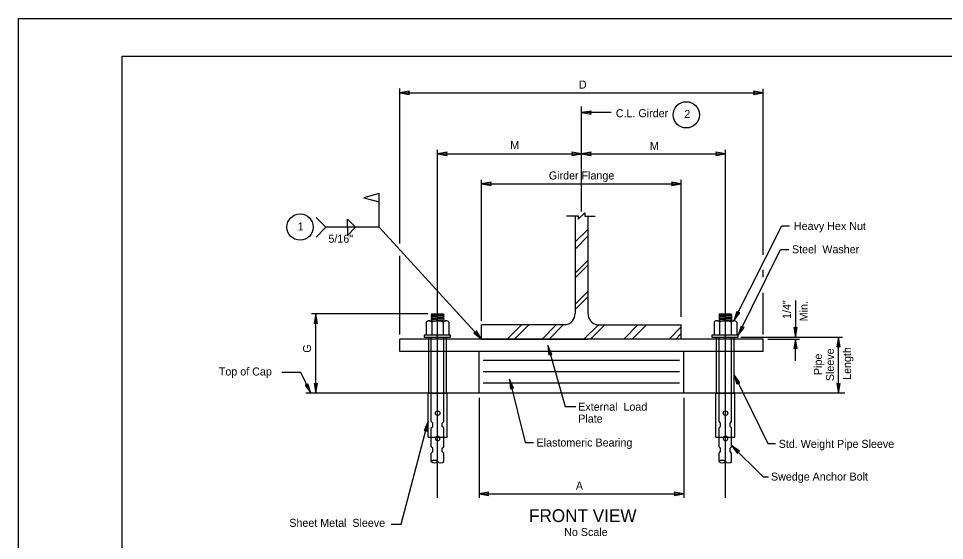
# Model space of a CAD drawing. Extents: x -193 to 149, y 507 to 725.
# Drawn here: x -192.5 to -47.9, y 643.6 to 725.2 of the extents above; entities that cross this region are included whole.
import ezdxf

# ---------------------------------------------------------------- set-up
doc = ezdxf.new("R2010")
doc.units = 0
for name, color, linetype in [('border', 7, 'Continuous'), ('Border 2660-Hwy18 - Level 62', 7, 'Continuous'), ('Level 20', 7, 'Continuous'), ('Level 21', 7, 'Continuous'), ('Level 31', 7, 'Continuous'), ('Level 40', 7, 'Continuous'), ('Level 41', 7, 'Continuous'), ('Level 42', 7, 'Continuous'), ('Level 43', 7, 'Continuous')]:
    doc.layers.add(name, color=color, linetype=linetype)

msp = doc.modelspace()

# ---------------------------------------------------------------- linework, layer by layer
at = {"layer": 'border'}
for p, q in [((-176.33, 719.31), (143.78, 719.31)), ((-176.33, 513.86), (-176.33, 719.31))]:
    msp.add_line(p, q, dxfattribs=at)
at = {"layer": 'Border 2660-Hwy18 - Level 62'}
msp.add_lwpolyline([(-192.53, 725.17), (148.65, 725.17), (148.65, 507.07), (-192.53, 507.07)], close=True, dxfattribs=at)
at = {"layer": 'Level 20'}
for p, q in [((-104.63, 695), (-104.63, 711.42)), ((-127.1, 650.25), (-127.1, 704.67)), ((-82.15, 650.25), (-82.15, 704.67))]:
    msp.add_line(p, q, dxfattribs=at)
at = {"layer": 'Level 21'}
msp.add_line((-63.52, 666.64), (-147.67, 666.64), dxfattribs=at)
at = {"layer": 'Level 31'}
for p, q in [((-105.61, 694.36), (-105.61, 679.08)), ((-103.64, 694.26), (-103.64, 679.08)), ((-128.02, 679), (-128.08, 678.89)), ((-128.08, 678.89), (-126.12, 678.89)), ((-128.08, 678.87), (-128.08, 678.89)), ((-126.16, 678.79), (-128.08, 678.88)), ((-126.16, 678.59), (-128.08, 678.68)), ((-126.16, 678.41), (-128.08, 678.5)), ((-126.16, 678.22), (-128.08, 678.32)), ((-128.02, 679), (-126.2, 679)), ((-126.2, 679), (-126.12, 678.89)), ((-126.12, 678.87), (-126.12, 678.89)), ((-83.07, 679), (-83.14, 678.89)), ((-83.14, 678.89), (-81.17, 678.89)), ((-83.14, 678.87), (-83.14, 678.89)), ((-81.21, 678.79), (-83.14, 678.88)), ((-81.21, 678.59), (-83.14, 678.68)), ((-81.21, 678.41), (-83.14, 678.5)), ((-81.21, 678.22), (-83.14, 678.32)), ((-83.07, 679), (-81.25, 679)), ((-81.25, 679), (-81.17, 678.89)), ((-81.17, 678.87), (-81.17, 678.89)), ((-128.87, 677.71), (-128.87, 675.67)), ((-128.44, 677.95), (-125.75, 677.95)), ((-126.16, 678.04), (-128.08, 678.13)), ((-128.01, 677.71), (-128.01, 675.67)), ((-126.2, 677.71), (-126.2, 675.67)), ((-125.33, 677.71), (-125.33, 675.67)), ((-107.08, 677.32), (-120.21, 677.32)), ((-120.21, 675.09), (-120.21, 677.32)), ((-102.17, 677.32), (-89.04, 677.32)), ((-89.04, 675.09), (-89.04, 677.32)), ((-83.92, 677.71), (-83.92, 675.67)), ((-83.49, 677.95), (-80.8, 677.95)), ((-81.21, 678.04), (-83.14, 678.13)), ((-83.06, 677.71), (-83.06, 675.67)), ((-81.25, 677.71), (-81.25, 675.67)), ((-80.38, 677.71), (-80.38, 675.67)), ((-128.48, 673.12), (-128.48, 675.38)), ((-128.2, 675.38), (-126.03, 675.38)), ((-128.08, 673.12), (-128.08, 675.38)), ((-126.12, 673.12), (-126.12, 675.38)), ((-125.72, 673.12), (-125.72, 675.38)), ((-83.53, 673.12), (-83.53, 675.38)), ((-83.25, 675.38), (-81.08, 675.38)), ((-83.14, 673.12), (-83.14, 675.38)), ((-81.17, 673.12), (-81.17, 675.38)), ((-80.77, 673.12), (-80.77, 675.38)), ((-76.25, 675.09), (-133, 675.09)), ((-133, 673.12), (-133, 675.09)), ((-120.21, 675.09), (-103.64, 675.09)), ((-89.04, 675.09), (-105.61, 675.09)), ((-76.25, 673.12), (-76.25, 675.09)), ((-76.25, 673.12), (-133, 673.12)), ((-128.48, 666.64), (-128.48, 673.12)), ((-128.08, 666.64), (-128.08, 673.12)), ((-126.12, 666.64), (-126.12, 673.12)), ((-125.72, 666.64), (-125.72, 673.12)), ((-120.61, 666.64), (-120.61, 673.12)), ((-88.65, 666.64), (-88.65, 673.12)), ((-83.53, 666.64), (-83.53, 673.12)), ((-83.14, 666.64), (-83.14, 673.12)), ((-81.17, 666.64), (-81.17, 673.12)), ((-80.77, 666.64), (-80.77, 673.12)), ((-119.96, 671.79), (-89.29, 671.79)), ((-119.96, 670.02), (-89.29, 670.02)), ((-119.96, 668.25), (-89.29, 668.25)), ((-128.57, 659.75), (-128.57, 666.64)), ((-128.57, 666.64), (-125.62, 666.64)), ((-128.48, 666.64), (-125.72, 666.64)), ((-128.08, 662.22), (-128.08, 666.64)), ((-126.12, 662.22), (-126.12, 666.64)), ((-125.62, 659.75), (-125.62, 666.64)), ((-83.62, 659.75), (-83.62, 666.64)), ((-83.62, 666.64), (-80.67, 666.64)), ((-83.53, 666.64), (-80.77, 666.64)), ((-83.14, 662.22), (-83.14, 666.64)), ((-81.17, 662.22), (-81.17, 666.64)), ((-80.67, 659.75), (-80.67, 666.64)), ((-127.84, 661.95), (-128.08, 662.22)), ((-128.08, 661.19), (-127.84, 661.44)), ((-128.08, 659.75), (-128.08, 661.19)), ((-127.84, 661.44), (-127.84, 661.95)), ((-126.37, 661.95), (-126.12, 662.22)), ((-126.37, 661.44), (-126.37, 661.95)), ((-126.12, 661.19), (-126.37, 661.44)), ((-126.12, 659.75), (-126.12, 661.19)), ((-82.89, 661.95), (-83.14, 662.22)), ((-83.14, 661.19), (-82.89, 661.44)), ((-83.14, 659.75), (-83.14, 661.19)), ((-82.89, 661.44), (-82.89, 661.95)), ((-81.42, 661.95), (-81.17, 662.22)), ((-81.42, 661.44), (-81.42, 661.95)), ((-81.17, 661.19), (-81.42, 661.44)), ((-81.17, 659.75), (-81.17, 661.19)), ((-128.57, 659.75), (-125.62, 659.75)), ((-128.08, 658.26), (-128.08, 659.75)), ((-126.12, 658.26), (-126.12, 659.75)), ((-83.62, 659.75), (-80.67, 659.75)), ((-83.14, 658.26), (-83.14, 659.75)), ((-81.17, 658.26), (-81.17, 659.75)), ((-127.84, 658.01), (-128.08, 658.26)), ((-127.84, 657.51), (-127.84, 658.01)), ((-126.37, 658.01), (-126.12, 658.26)), ((-126.37, 657.51), (-126.37, 658.01)), ((-82.89, 658.01), (-83.14, 658.26)), ((-82.89, 657.51), (-82.89, 658.01)), ((-81.42, 658.01), (-81.17, 658.26)), ((-81.42, 657.51), (-81.42, 658.01)), ((-128.08, 657.24), (-127.84, 657.51)), ((-128.08, 655.95), (-128.08, 657.24)), ((-126.12, 657.24), (-126.37, 657.51)), ((-126.12, 655.95), (-126.12, 657.24)), ((-83.14, 657.24), (-82.89, 657.51)), ((-83.14, 655.95), (-83.14, 657.24)), ((-81.17, 657.24), (-81.42, 657.51)), ((-81.17, 655.95), (-81.17, 657.24))]:
    msp.add_line(p, q, dxfattribs=at)
for points in [[(-128.08, 678.87), (-128.05, 678.77), (-128.08, 678.68)], [(-128.08, 678.68), (-128.05, 678.59), (-128.08, 678.5)], [(-128.08, 678.5), (-128.05, 678.41), (-128.08, 678.32)], [(-128.08, 678.32), (-128.05, 678.22), (-128.08, 678.13)], [(-126.12, 678.87), (-126.16, 678.77), (-126.12, 678.68)], [(-126.12, 678.68), (-126.16, 678.59), (-126.12, 678.5)], [(-126.12, 678.5), (-126.16, 678.41), (-126.12, 678.32)], [(-126.12, 678.32), (-126.16, 678.22), (-126.12, 678.13)], [(-83.14, 678.87), (-83.1, 678.77), (-83.14, 678.68)], [(-83.14, 678.68), (-83.1, 678.59), (-83.14, 678.5)], [(-83.14, 678.5), (-83.1, 678.41), (-83.14, 678.32)], [(-83.14, 678.32), (-83.1, 678.22), (-83.14, 678.13)], [(-81.17, 678.87), (-81.21, 678.77), (-81.17, 678.68)], [(-81.17, 678.68), (-81.21, 678.59), (-81.17, 678.5)], [(-81.17, 678.5), (-81.21, 678.41), (-81.17, 678.32)], [(-81.17, 678.32), (-81.21, 678.22), (-81.17, 678.13)], [(-128.08, 678.13), (-128.05, 678.04), (-128.08, 677.95)], [(-126.12, 678.13), (-126.16, 678.04), (-126.12, 677.95)], [(-83.14, 678.13), (-83.1, 678.04), (-83.14, 677.95)], [(-81.17, 678.13), (-81.21, 678.04), (-81.17, 677.95)]]:
    msp.add_lwpolyline(points, dxfattribs=at)
for points in [[(-125.08, 675.38), (-125.08, 675.67), (-129.2, 675.67), (-129.2, 675.38)], [(-80.13, 675.38), (-80.13, 675.67), (-84.25, 675.67), (-84.25, 675.38)]]:
    msp.add_lwpolyline(points, close=True, dxfattribs=at)
for centre in [(-127.08, 663.51), (-82.13, 663.51)]:
    msp.add_circle(centre, 0.356, dxfattribs=at)
for centre, radius, start, end in [((-107.38, 679.06), 1.76, 279.5, 0), ((-101.87, 679.06), 1.76, 180, 260.5), ((-128.44, 677.44), 0.511, 32.004, 147.996), ((-127.1, 676.11), 1.84, 60.5577, 119.4423), ((-125.76, 677.44), 0.511, 32.004, 147.996), ((-83.49, 677.44), 0.511, 32.004, 147.996), ((-82.15, 676.11), 1.84, 60.5577, 119.4423), ((-80.81, 677.44), 0.511, 32.004, 147.996), ((-127.08, 659.56), 0.356, 147.5341, 32.4659), ((-127.08, 659.56), 0.356, 32.4659, 147.5341), ((-82.13, 659.56), 0.356, 147.5341, 32.4659), ((-82.13, 659.56), 0.356, 32.4659, 147.5341), ((-127.59, 655.38), 0.751, 49.0496, 130.9504), ((-127.59, 656.51), 0.751, 229.0496, 310.9504), ((-126.61, 656.51), 0.751, 229.0496, 310.9504), ((-82.64, 655.38), 0.751, 49.0496, 130.9504), ((-82.64, 656.51), 0.751, 229.0496, 310.9504), ((-81.66, 656.51), 0.751, 229.0496, 310.9504)]:
    msp.add_arc(centre, radius, start, end, dxfattribs=at)
at = {"layer": 'Level 40'}
msp.add_circle((-88.26, 710.12), 2.05, dxfattribs=at)
at = {"layer": 'Level 42'}
for p, q in [((-105.61, 690.25), (-103.64, 692.22)), ((-105.61, 689.15), (-103.64, 691.15)), ((-105.61, 685.4), (-103.64, 687.37)), ((-105.61, 684.64), (-103.64, 686.61)), ((-105.61, 680.52), (-103.64, 682.49)), ((-105.61, 679.71), (-103.64, 681.7)), ((-116.21, 675.09), (-113.98, 677.32)), ((-115.08, 675.09), (-112.85, 677.32)), ((-110.78, 675.09), (-108.56, 677.32)), ((-109.68, 675.09), (-107.46, 677.32)), ((-104.23, 675.09), (-101.99, 677.32)), ((-103.2, 675.09), (-100.97, 677.32)), ((-98.01, 675.09), (-95.8, 677.32)), ((-96.72, 675.09), (-94.48, 677.32)), ((-90.92, 675.09), (-89.04, 676.99)), ((-89.87, 675.09), (-89.04, 675.93))]:
    msp.add_line(p, q, dxfattribs=at)
at = {"layer": 'Level 43'}
for p, q in [((-133, 700.65), (-133, 714.21)), ((-133, 713.57), (-76.25, 713.57)), ((-76.25, 701.13), (-76.25, 714.19)), ((-99.98, 710.46), (-104.63, 710.46)), ((-127.1, 704.03), (-104.63, 704.03)), ((-104.63, 704.03), (-82.15, 704.03)), ((-133, 690.01), (-133, 700.65)), ((-120.21, 677.95), (-120.21, 699.98)), ((-89.04, 678.53), (-89.04, 699.98)), ((-76.25, 688.26), (-76.25, 701.13)), ((-120.21, 699.33), (-89.04, 699.33)), ((-136.21, 692.54), (-136.21, 697.81)), ((-144.55, 692.54), (-146.07, 694.06)), ((-141.17, 692.54), (-141.17, 693.8)), ((-141.17, 693.8), (-139.91, 692.54)), ((-144.55, 692.54), (-146.07, 691.02)), ((-141.17, 692.54), (-141.17, 691.28)), ((-141.17, 691.28), (-139.91, 692.54)), ((-133, 675.82), (-133, 688.09)), ((-76.25, 684.74), (-76.25, 685.89)), ((-76.25, 675.82), (-76.25, 682.28)), ((-71.21, 681.09), (-71.21, 675.38)), ((-128.64, 679), (-146.77, 679)), ((-146.12, 666.64), (-146.12, 679)), ((-79.74, 675.38), (-63.84, 675.38)), ((-78.98, 675.38), (-70.46, 675.38)), ((-64.48, 666.64), (-64.48, 675.38)), ((-75.5, 675.09), (-70.57, 675.09)), ((-71.21, 671.66), (-71.21, 675.09)), ((-120.61, 665.89), (-120.61, 650.25)), ((-88.65, 665.89), (-88.65, 650.25)), ((-120.61, 650.89), (-88.65, 650.89))]:
    msp.add_line(p, q, dxfattribs=at)
for points in [[(-133, 713.57), (-131.5, 713.32), (-131.63, 713.57), (-131.5, 713.82)], [(-76.25, 713.57), (-77.75, 713.82), (-77.62, 713.57), (-77.75, 713.32)], [(-104.63, 710.46), (-103.13, 710.21), (-103.26, 710.46), (-103.13, 710.71)], [(-127.1, 704.03), (-125.6, 703.78), (-125.73, 704.03), (-125.6, 704.28)], [(-104.63, 704.03), (-106.13, 704.28), (-106, 704.03), (-106.13, 703.78)], [(-104.63, 704.03), (-103.13, 703.78), (-103.26, 704.03), (-103.13, 704.28)], [(-82.15, 704.03), (-83.65, 704.28), (-83.52, 704.03), (-83.65, 703.78)], [(-120.21, 699.33), (-118.71, 699.08), (-118.84, 699.33), (-118.71, 699.58)], [(-89.04, 699.33), (-90.54, 699.58), (-90.41, 699.33), (-90.54, 699.08)], [(-136.21, 697.81), (-138.63, 697.16), (-136.21, 696.51)], [(-146.12, 679), (-146.37, 677.5), (-146.12, 677.63), (-145.87, 677.5)], [(-80.81, 677.95), (-79.91, 679.17), (-80.2, 679.17), (-80.36, 679.4)], [(-80.13, 675.67), (-79.24, 676.9), (-79.53, 676.89), (-79.69, 677.12)], [(-71.21, 675.38), (-70.96, 676.88), (-71.21, 676.75), (-71.46, 676.88)], [(-120.21, 675.09), (-121.04, 676.36), (-121.14, 676.1), (-121.41, 676.03)], [(-64.48, 675.38), (-64.73, 673.88), (-64.48, 674.01), (-64.23, 673.88)], [(-109.9, 674.06), (-109.73, 672.55), (-109.52, 672.75), (-109.25, 672.69)], [(-71.21, 675.09), (-71.46, 673.59), (-71.21, 673.72), (-70.96, 673.59)], [(-146.91, 666.64), (-147.34, 668.1), (-147.51, 667.87), (-147.79, 667.88)], [(-146.12, 666.64), (-145.87, 668.14), (-146.12, 668.01), (-146.37, 668.14)], [(-115.84, 668.8), (-115.73, 667.29), (-115.52, 667.47), (-115.24, 667.41)], [(-80.77, 669.47), (-80.34, 668.02), (-80.17, 668.24), (-79.89, 668.24)], [(-64.48, 666.64), (-64.23, 668.14), (-64.48, 668.01), (-64.73, 668.14)], [(-128.57, 662.18), (-129.19, 660.79), (-128.92, 660.85), (-128.71, 660.66)], [(-81.17, 658.45), (-80.28, 657.22), (-80.2, 657.48), (-79.93, 657.57)], [(-120.61, 650.89), (-119.11, 650.64), (-119.24, 650.89), (-119.11, 651.14)], [(-88.65, 650.89), (-90.15, 651.14), (-90.02, 650.89), (-90.15, 650.64)]]:
    msp.add_lwpolyline(points, close=True, dxfattribs=at)
for points in [[(-106.94, 694.36), (-105.13, 694.36), (-105.13, 693.81), (-104.11, 694.82), (-104.11, 694.26), (-102.47, 694.26)], [(-80.81, 677.95), (-73.34, 692.75), (-72.15, 692.75)], [(-120.21, 675.09), (-136.21, 692.54), (-144.55, 692.54)], [(-80.13, 675.67), (-73.52, 689.07), (-72.26, 689.07)], [(-109.9, 674.06), (-107.16, 664.55), (-105.52, 664.55)], [(-146.91, 666.64), (-148.47, 669.84), (-151.43, 669.84)], [(-115.84, 668.8), (-113.4, 658.92), (-112.09, 658.91)], [(-80.77, 669.47), (-75.5, 658.75), (-74.31, 658.75)], [(-134.33, 646.17), (-132.79, 646.17), (-128.57, 662.18)], [(-81.17, 658.45), (-76.27, 653.57), (-75.4, 653.57)]]:
    msp.add_lwpolyline(points, dxfattribs=at)
msp.add_circle((-148.57, 692.58), 2.05, dxfattribs=at)

# ---------------------------------------------------------------- texts
at = {"layer": 'Level 40'}
for s, p in [('D', (-105.02, 714.22)), ('C.L. Girder', (-99.26, 709.75)), ('2', (-88.57, 709.63)), ('M', (-115.74, 704.76)), ('M', (-93.94, 704.64)), ('Girder Flange', (-109.72, 700.02)), ('1', (-148.96, 692.05)), ('Heavy Hex Nut', (-71.45, 692.12)), ('5/16"', (-144.14, 690.14)), ('Steel  Washer', (-71.75, 688.49)), ('Top of Cap', (-161.25, 669.39)), ('External  Load ', (-105.13, 663.89)), ('Plate', (-105.13, 662.03)), ('Elastomeric Bearing', (-111.63, 658.29)), ('Std. Weight Pipe Sleeve ', (-73.82, 658.08)), ('Swedge Anchor Bolt ', (-75.03, 652.97)), ('A', (-105.5, 651.54)), ('Sheet Metal  Sleeve', (-150.25, 645.74)), ('No Scale', (-107.32, 644.31))]:
    msp.add_text(s, height=1.25, dxfattribs=at).set_placement(p)
for s, p in [('1/4"', (-71.93, 678.22)), ('Min.', (-69.3, 677.86)), ('G', (-146.85, 672.95)), ('Pipe', (-67.07, 669.46)), ('Sleeve', (-65.2, 668.51)), ('Length', (-62.53, 668.7))]:
    msp.add_text(s, height=1.25, rotation=90, dxfattribs=at).set_placement(p)
at = {"layer": 'Level 41'}
msp.add_text(' FRONT VIEW ', height=2, dxfattribs=at).set_placement((-113.56, 646.49))

doc.saveas('drawing.dxf')
